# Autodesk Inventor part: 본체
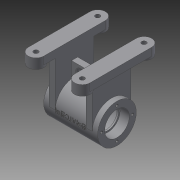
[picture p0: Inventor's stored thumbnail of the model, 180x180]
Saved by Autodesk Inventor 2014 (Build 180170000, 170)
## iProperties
Created: 2015-11
Part Number: 본체
Material: Generic
Document SubType Name: Modeling
Designer: user
Density: 1 g/cm^3
Appearance: Default
Author: user
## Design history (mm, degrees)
sketch "Sketch1"
  geometry: L1 (0, 0)-(20, 0); L2 (20, 0)-(20, 80); L3 (20, 80)-(0, 80); L4 (0, 80)-(0, 0); L5 (60, 80)-(80, 80); L6 (80, 80)-(80, 0); L7 (80, 0)-(60, 0); L8 (60, 0)-(60, 80)
  constraints: 16 end point, 4 parallel, 2 equal length, 2 horizontal, 2 perpendicular, 1 collinear
  dimensions: "d0" = 80 distance of L3.end L1.start; "d1" = 20 distance of L2.end L3.end; "d2" = 80 distance between parallel lines of L6 L4
extrude "Extrusion1" new body sketch "Sketch1" distance "d3" = 10; taper "d4" = 0 deg
sketch "Sketch2"
  geometry: L1 (20, 0)-(20, 80) reference; L2 (80, 0)-(80, 80) reference; C1 r 10 at (10, 0); C2 r 10 at (70, 0); 1 further point
  constraints: 2 centre point
  dimensions: "d5" = 20 diameter of C1; "d6" = 10 distance from line of L1 C1.centre; "d7" = 20 diameter of C2; "d8" = 10 distance from line of L2 C2.centre
extrude "Extrusion2" join sketch "Sketch2" distance "d9" = 13; taper "d10" = 0 deg
workplane "Work Plane1"
mirror "Mirror1"
workplane "Work Plane2"
sketch "Sketch3"
  geometry: L1 (0, 10)-(80, 10) reference; L2 (90, -3)-(90, 10) reference; C1 r 25 at (40, -58); 1 further point
  constraints: 1 centre point
  dimensions: "d13" = 50 diameter of C1; "d14" = 68 distance from line of L1 C1.centre; "d15" = 50 distance from line of L2 C1.centre
extrude "Extrusion3" join sketch "Sketch3" distance "d16" = 70; taper "d17" = 0 deg
sketch "Sketch4"
  geometry: L1 (-60, 80)-(-60, 0) reference; L2 (-80, 0)-(-80, 80) reference; L3 (0, 80)-(0, 0) reference; L4 (-20, 0)-(-20, 80) reference; L5 (-60, 15)-(-68, 15); L6 (-68, 15)-(-68, 65); L7 (-68, 65)-(-60, 65); L8 (-20, 65)-(-12, 65); L9 (-12, 65)-(-12, 15); L10 (-12, 15)-(-20, 15); L11 (-20, 65)-(-20, 15); L12 (-60, 65)-(-60, 15); A1 r 10 centre (-70, 0) between (-80, 0) and (-60, 0) reference; A2 r 10 centre (-70, 80) between (-60, 80) and (-80, 80) reference; A3 r 10 centre (-10, 0) between (-20, 0) and (0, 0) reference; A4 r 10 centre (-10, 80) between (0, 80) and (-20, 80) reference; 1 further point
  constraints: 16 end point, 5 perpendicular, 4 point on line, 3 collinear
  dimensions: "d18" = 8 distance between parallel lines of L12 L6; "d19" = 8 distance between parallel lines of L9 L11; "d20" = 50 distance of L5.end L6.end; "d21" = 50 distance of L8.end L9.end; "d22" = 15 distance from line of A1.centre L5; "d23" = 15 distance from line of A3.centre L10
extrude "Extrusion4" join sketch "Sketch4" stored distance "d24" = 70; taper "d25" = 0 deg
workplane "Work Plane3"
sketch "Sketch5"
  geometry: L1 (75, 15)-(75, 65) reference; L2 (12, 65)-(20, 65) reference; L3 (20, 65)-(20, 15) reference; L4 (12, 15)-(20, 15) reference; L5 (12, 15)-(12, 65) reference; L6 (5, 65)-(5, 15) reference; L7 (60, 15)-(68, 15) reference; L8 (60, 15)-(60, 65) reference; L9 (60, 65)-(68, 65) reference; L10 (68, 65)-(68, 15) reference; C1 r 5 at (40, 40); 1 further point
  constraints: 1 centre point
  dimensions: "d27" = 10 diameter of C1; "d36" = 25 distance from line of C1.centre L7; "d76" = 35 distance from line of C1.centre L1
extrude "Extrusion5" join sketch "Sketch5" stored distance "d28" = 70; taper "d29" = 0 deg
workplane "Work Plane4"
sketch "Sketch6"
  geometry: L1 (60, 15)-(68, 15) reference; L2 (60, 15)-(60, 65) reference; L3 (60, 65)-(68, 65) reference; L4 (68, 65)-(68, 15) reference; L5 (5, 65)-(5, 15) reference; L6 (12, 65)-(20, 65) reference; L7 (20, 65)-(20, 15) reference; L8 (12, 15)-(20, 15) reference; L9 (12, 15)-(12, 65) reference; L10 (75, 15)-(75, 65) reference; L11 (20, 44)-(60, 44); L12 (60, 44)-(60, 36); L13 (60, 36)-(20, 36); L14 (20, 36)-(20, 44); 3 further points
  constraints: 8 end point, 2 collinear, 2 parallel, 1 horizontal, 1 midpoint, 1 perpendicular, 1 other
  dimensions: "d32" = 25 distance from line of L3 point (60, 40); "d33" = 8 distance of L13.end L11.start
extrude "Extrusion6" join sketch "Sketch6" stored distance "d34" = 70; taper "d35" = 0 deg
sketch "Sketch7"
  geometry: L1 (12, 10)-(28, 10); L2 (12, 6.5)-(28, 6.5); L3 (28, 13.5)-(12, 13.5); L4 (40, -23)-(60, -23) reference; L5 (-15, 70)-(-15, 20) reference; A1 r 3.5 centre (12, 10) between (12, 13.5) and (12, 6.5); A2 r 3.5 centre (28, 10) between (28, 6.5) and (28, 13.5); 2 further points
  constraints: 8 end point, 4 point on circle, 4 tangent, 2 centre point, 1 horizontal, 1 midpoint, 1 parallel
  dimensions: "d37" = 3.5 radius of A2; "d38" = 33 distance from line of L4 point (20, 10); "d40" = 23 dimension on A2 A1; "d41" = 35 distance from line of point (20, 10) L5
extrude "Extrusion7" cut sketch "Sketch7" stored distance "d42" = 70; taper "d43" = 0 deg
hole "Hole1" diameter "d46" = 28; stored, may be unused: countersink angle "d50" = 90 deg, drill point angle "d52" = 0 deg; dims "d47" = 6, "d48" = 32, "d49" = 12, "d51" = 14, "d53" = 10, "d54" = 10
workplane "Work Plane5"
mirror "Mirror2"
workplane "Work Plane6"
sketch "Sketch8"
  geometry: C1 r 21 at (0, 0); 1 further point
  constraints: 1 centre point
  dimensions: "d56" = 42 diameter of C1
extrude "Extrusion8" cut sketch "Sketch8" distance "d57" = 42; taper "d58" = 0 deg
sketch "Sketch9"
  geometry: 2 further points
hole "Hole2" sketch "Sketch9" at (-20, 0) diameter "d60" = 3.242; stored, may be unused: countersink angle "d64" = 90 deg, drill point angle "d66" = 118 deg; dims "d61" = 8, "d62" = 4, "d63" = 8, "d65" = 10
pattern_circular "Circular Pattern1" dims angle "d68" = 360 deg
workplane "Work Plane7"
mirror "Mirror3"
workplane "Work Plane9"
  workplane "Work Plane8"
sketch "Sketch10"
  geometry: L1 (-7, -83)-(63, -83) reference; L2 (63, -83)-(63, -33) reference; 3 further points
  constraints: 1 other
  dimensions: "d77" = 25 distance from line of point (28, -58) L1; "d78" = 35 distance from line of point (28, -58) L2
emboss "Emboss1" sketch "Sketch10" dims "d79" = 0.5, "d80" = 0
hole "Hole3" diameter "d83" = 6; stored, may be unused: countersink angle "d87" = 90 deg, drill point angle "d89" = 0 deg; dims "d84" = 6, "d85" = 4, "d86" = 8, "d88" = 10, "d90" = 10, "d91" = 10
workplane "Work Plane11"
sketch "Sketch11"
  geometry: L1 (-58, 25)-(-33.751, 39); L2 (-58, 25)-(-30, 25); C1 r 14 at (-58, 25) reference; 1 further point
  constraints: 4 end point, 1 equal length, 1 horizontal
  dimensions: "d92" = 28 distance of L1.start L1.end; "d93" = 30 deg angle of L2 L1
workplane "Work Plane12"
sketch "Sketch12"
  geometry: L1 (0, 0)-(28, 0) reference; L2 (28, 0)-(22.856, 0); L3 (22.856, 0)-(22.856, 6); L4 (22.856, 6)-(28, 6); L5 (28, 6)-(28, 0); 1 further point
  constraints: 8 end point, 2 parallel, 1 horizontal, 1 perpendicular
  dimensions: "d95" = 6 distance of L2.end L3.end
revolve "Revolution1" sketch "Sketch12" stored, may be unused: angle "d96" = 90 deg
hole "Hole4" diameter "d99" = 6; stored, may be unused: countersink angle "d103" = 90 deg, drill point angle "d105" = 0 deg; dims "d97" = 10, "d98" = 10, "d100" = 6, "d101" = 12, "d102" = 4, "d104" = 10
pattern_linear "Rectangular Pattern1" dims "d112" = 60
fillet "Fillet1" dims "d106" = 0.3
chamfer "Chamfer1" distance "d107" = 1; stored, may be unused: second distance "d108" = 2, angle "d109" = 45 deg
fillet "Fillet2" dims "d116" = 3.5
body "Solid1"
node "Projected Loop1"
node "Projected Loop2"
node "Projected Loop3"
node "Projected Loop4"
other parameters: "d12" = 5, "d26" = -96, "d30" = -23, "d55" = -14, "d73" = 25.5, "d94" = 90 deg
